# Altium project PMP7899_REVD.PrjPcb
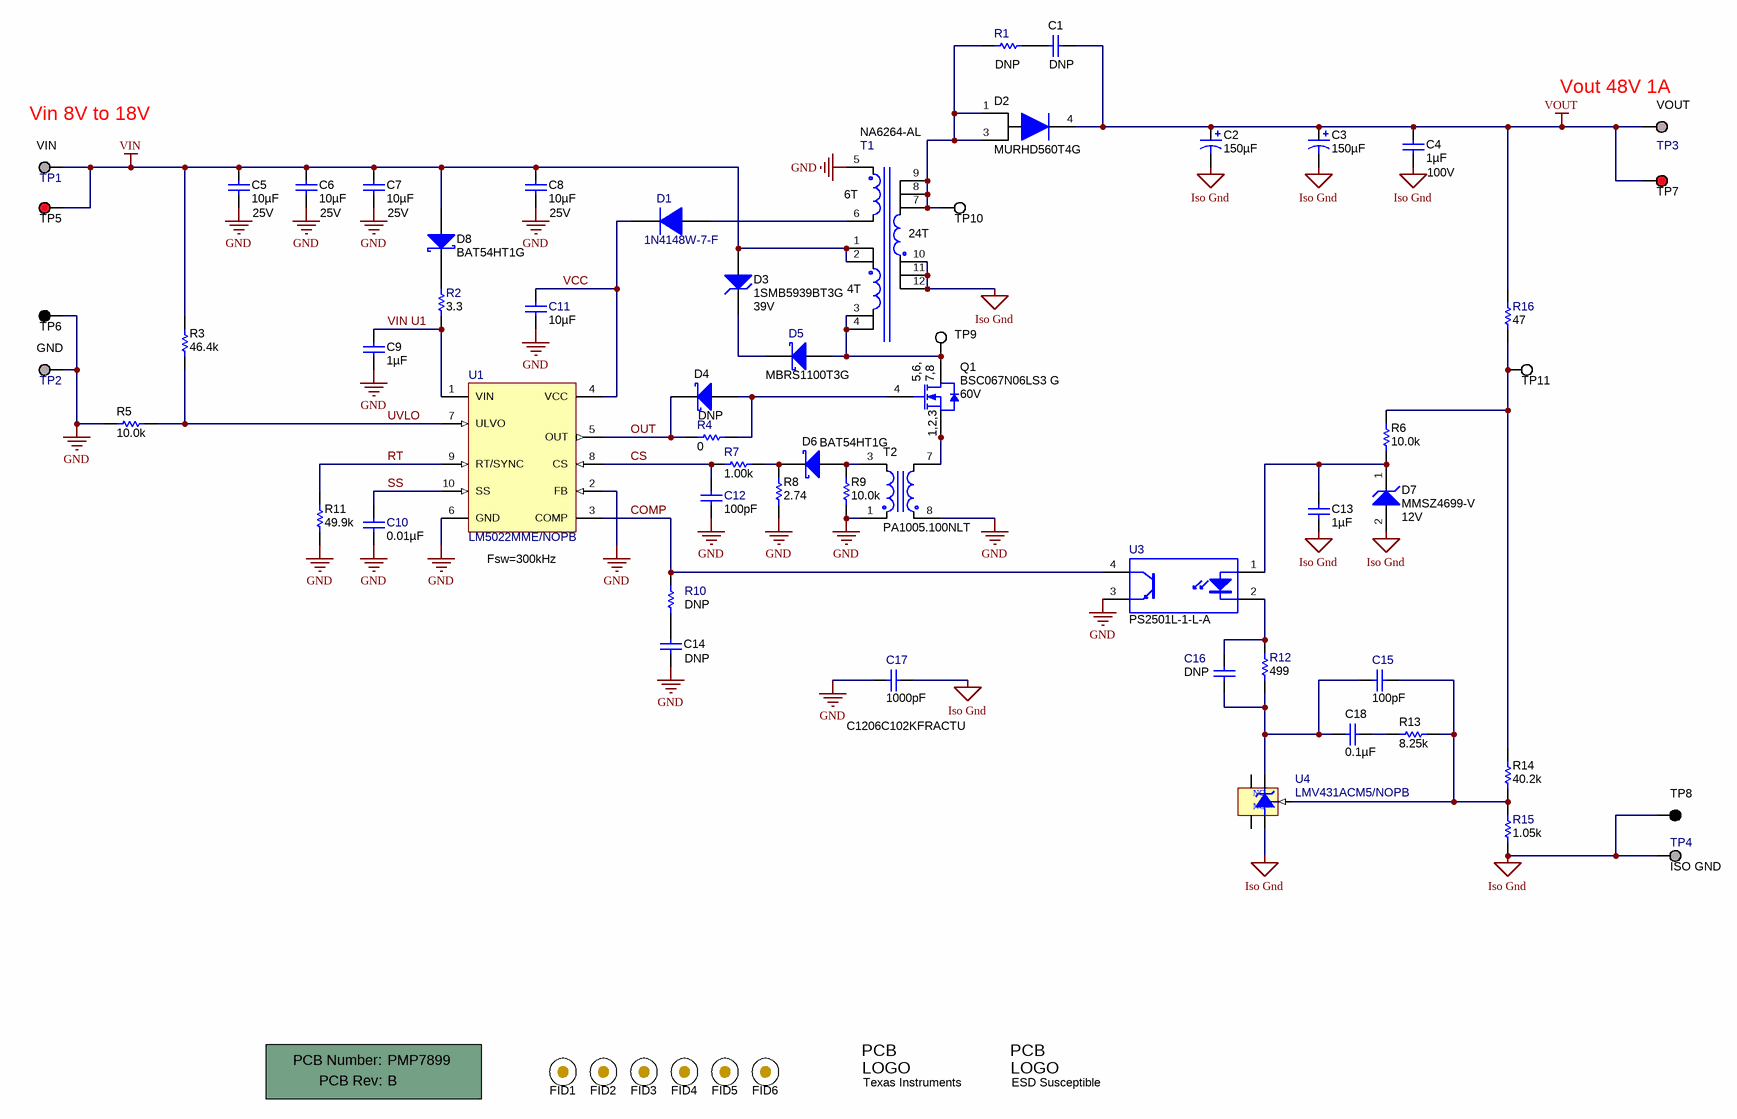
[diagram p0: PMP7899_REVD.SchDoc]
TID: PMP7899; TechSupport: http://www.ti.com/support; SCH_Rev: D; PRJ_Title: LM5022 Flyback; PRJ_Number: PMP7899; PRJ_Engineer: David Baba; PRJ_Customer: Public Release; PCB_Rev: B; PCB_Layout: Dee Lim; EVM_Orderable: N/A; CopyrightYear: 2015
1 sheet, 68 parts. Net scope: global (net labels, ports and power ports of the same name join across sheets).
Board file: PMP7899_REVB.PcbDoc

## Sheet PMP7899_REVD.SchDoc
size 431 x 279 mm; Date: Not shown in title block; ApprovedBy: Not shown in title block; CheckedBy: Not shown in title block; Author: Not shown in title block; CompanyName: Not shown in title block; Engineer: Not shown in title block; Organization: Not shown in title block; Address1: Not shown in title block; Address2: Not shown in title block; Address3: Not shown in title block; Address4: Not shown in title block; DocumentNumber: 1; Revision: Use project parameter SCH_Rev; SheetNumber: 1; SheetTotal: 1; PageSetup: Record=PageOptions¦CenterHorizontal=True¦CenterVertical=True¦PrintScale=1.00¦XCorrection=1.00¦YCorrection=1.00¦PrintKind=0¦BorderSize=5000000¦LeftOffset=0¦BottomOffset=0¦Orientation=2¦PaperLength=1000¦PaperWidth=1000¦Scale=100¦PaperSource=15¦PrintQuality=600¦MediaType=1¦DitherType=10¦PaperKind=Letter¦PrintScaleMode=1

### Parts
!PCB  Printed Circuit Board  (value not drawn)  (mechanical)
C1  DNP  [0603]
C2  ValueDisplayed: 150µF  [SM_RADIAL_H13]  (hidden comment: EEV-FK1J151Q)
C3  ValueDisplayed: 150µF  [SM_RADIAL_H13]  (hidden comment: EEV-FK1J151Q)
C4  ValueDisplayed: 1µF  Value2: 100V  [1206]  (hidden comment: C3216X7R2A105M)
C5  ValueDisplayed: 10µF  VDC_V: 25V  [1206]  (hidden comment: GRM31CR71E106KA12L)
C6  ValueDisplayed: 10µF  VDC_V: 25V  [1206]  (hidden comment: GRM31CR71E106KA12L)
C7  ValueDisplayed: 10µF  VDC_V: 25V  [1206]  (hidden comment: GRM31CR71E106KA12L)
C8  ValueDisplayed: 10µF  VDC_V: 25V  [1206]  (hidden comment: GRM31CR71E106KA12L)
C9  ValueDisplayed: 1µF  [0805_HV]  (hidden comment: C2012X5R1E105K)
C10  ValueDisplayed: 0.01µF  [0805_HV]  (hidden comment: C2012C0G1E103J)
C11  ValueDisplayed: 10µF  [1206]  (hidden comment: GRM31CR61E106KA12L)
C12  ValueDisplayed: 100pF  [0603]  (hidden comment: C1608C0G1H101J)
C13  ValueDisplayed: 1µF  [0603]  (hidden comment: GRM188R61C105KA93D)
C14  DNP  [0603]
C15  ValueDisplayed: 100pF  [0603]  (hidden comment: C1608C0G2A101J)
C16  DNP  [0805_HV]
C17  C1206C102KFRACTU  ValueDisplayed: 1000pF  [1206]
C18  ValueDisplayed: 0.1µF  [0603]  (hidden comment: C0603C104J3RACTU)
D1  1N4148W-7-F  [SOD-123]
D2  MURHD560T4G  [DPAK]
D3  1SMB5939BT3G  value 39V  [SMB]
D4  DNP  [sod-323]
D5  MBRS1100T3G  [SMB]
D6  BAT54HT1G  [sod-323]
D7  MMSZ4699-V  value 12V  [SOD-123]
D8  BAT54HT1G  [sod-323]
FID1  Fiducial  [Fiducial10-20]  (value not drawn)
FID2  Fiducial  [Fiducial10-20]  (value not drawn)
FID3  Fiducial  [Fiducial10-20]  (value not drawn)
FID4  Fiducial  [Fiducial10-20]  (value not drawn)
FID5  Fiducial  [Fiducial10-20]  (value not drawn)
FID6  Fiducial  [Fiducial10-20]  (value not drawn)
Logo1  Texas Instruments  [TI_Symbol_Overlay_Small]  (no BOM)
Logo2  ESD Susceptible  [ESD_Overlay_Small]  (no BOM)
Q1  BSC067N06LS3 G  value 60V  [PG-TDSON-8]
R1  DNP  [1206]
R2  ValueDisplayed: 3.3  [1206]  (hidden comment: CRCW12063R30JNEA)
R3  value 46.4k  [0603]  (hidden comment: CRCW060346K4FKEA)
R4  value 0  [1206]  (hidden comment: CRCW12060000Z0EA)
R5  value 10.0k  [0603]  (hidden comment: CRCW060310K0FKEA)
R6  value 10.0k  [0805_HV]  (hidden comment: CRCW080510K0FKEA)
R7  value 1.00k  [0603]  (hidden comment: CRCW06031K00FKEA)
R8  ValueDisplayed: 2.74  [0603]  (hidden comment: CRCW06032R74FKEA)
R9  value 10.0k  [0603]  (hidden comment: CRCW060310K0FKEA)
R10  DNP  [0603]
R11  value 49.9k  [0603]  (hidden comment: CRCW060349K9FKEA)
R12  value 499  [0805_HV]  (hidden comment: CRCW0805499RFKEA)
R13  ValueDisplayed: 8.25k  [0603]  (hidden comment: CRCW06038K25FKEA)
R14  value 40.2k  [0603]  (hidden comment: CRCW060340K2FKEA)
R15  ValueDisplayed: 1.05k  [0603]  (hidden comment: CRCW06031K05FKEA)
R16  ValueDisplayed: 47  [0805_HV]  (hidden comment: ERJ-6GEYJ470V)
T1  NA6264-AL  [NA62XX-AL]
T2  PA1005.100NLT  [PA1005.XXXNL]
TP1  VIN  [Keystone1502-2]
TP2  GND  [Keystone1502-2]
TP3  VOUT  [Keystone1502-2]
TP4  ISO GND  [Keystone1502-2]
TP5  5000  [Keystone5000]  (value not drawn)
TP6  5001  [Keystone5001]  (value not drawn)
TP7  5000  [Keystone5000]  (value not drawn)
TP8  5001  [Keystone5001]  (value not drawn)
TP9  5002  [Keystone5002]  (value not drawn)
TP10  5002  [Keystone5002]  (value not drawn)
TP11  5002  [Keystone5002]  (value not drawn)
U1  LM5022MME/NOPB  [MUB10A_N]
U3  PS2501L-1-L-A  [PS2501L]
U4  LMV431ACM5/NOPB  [MF05A_N]

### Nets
GND: C5.2 C6.2 C7.2 C8.2 C9.2 C10.2 C11.2 C12.2 C14.2 C17.2 R5.1 R8.1 R9.1 R11.1 T1.5 T2.1 T2.8 TP2.1 TP6.1 U1.2(FB) U1.6(GND) U3.3(E)
Iso Gnd: C2.2(-) C3.2(-) C4.2 C13.2 C17.1 D7.2(A) R15.2 T1.10 T1.11 T1.12 TP4.1 TP8.1 U4.5(A)
VIN: C5.1 C6.1 C7.1 C8.1 D3.2(A) D8.2(A) R3.2 T1.1 T1.2 TP1.1 TP5.1
VOUT: C1.1 C2.1(+) C3.1(+) C4.1 D2.4 R16.2 TP3.1 TP7.1
COMP: R10.1 U1.3(COMP) U3.4(C)
CS: C12.1 R7.1 U1.8(CS)
OUT: D4.1(K) R4.2 U1.5(OUT)
RT: R11.2 U1.9(RT/SYNC)
SS: C10.1 U1.10(SS)
UVLO: R3.1 R5.2 U1.7(ULVO)
VCC: C11.1 D1.1(K) U1.4(VCC)
VIN U1: C9.1 R2.1 U1.1(VIN)
NetC1_2: C1.2 R1.1
NetC13_1: C13.1 D7.1(K) R6.1 U3.1(A)
NetC14_1: C14.1 R10.2
NetC15_1: C15.1 C16.1 C18.2 R12.2 U4.3(K)
NetC15_2: C15.2 R13.1 R14.1 R15.1 U4.4(REF)
NetC16_2: C16.2 R12.1 U3.2(K)
NetC18_1: C18.1 R13.2
NetD1_2: D1.2(A) T1.6
NetD2_1: D2.1 D2.3 R1.2 T1.7 T1.8 T1.9 TP10.1
NetD3_1: D3.1(K) D5.1(K)
NetD4_2: D4.2(A) Q1.4(G) R4.1
NetD5_2: D5.2(A) Q1.5(D) Q1.6(D) Q1.7(D) Q1.8(D) Q1.9(D) T1.3 T1.4 TP9.1
NetD6_1: D6.1(K) R7.2 R8.2
NetD6_2: D6.2(A) R9.2 T2.3
NetD8_1: D8.1(K) R2.2
NetQ1_1: Q1.1(S) Q1.2(S) Q1.3(S) T2.7
NetR6_2: R6.2 R14.2 R16.1 TP11.1

Not connected (* = marked no-connect by the designer): U4 1(NC) 2(NC)

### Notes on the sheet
- (near TP1) Vin 8V to 18V
- (near TP3) Vout 48V 1A
- (near U1) Fsw=300kHz

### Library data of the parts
!PCB = PCB: Manufacturer: Any; PartNumber: PMP7899; SymbolCreator: a0412235
C1 = C1608C0G2A101J: CAP, CERM, 100pF, 100V, +/-5%, C0G/NP0, 0603; Manufacturer: TDK; Polarized: N; CompType: Capacitor; U/M: EA; Cap_F: 0.0000000001; Tolerance_%: 5; ESR_Ohm: 0.1202; Value1: 0.1202 ohm; VDC_V: 100; TaMin_C: -55; TaMax_C: 125
C2 C3 = EEV-FK1J151Q: CAP, AL, 150uF, 63V, +/-20%, 0.16 ohm, SMD; Manufacturer: Panasonic; Polarized: Y; CompType: Capacitor; U/M: EA; Cap_F: 0.00015; Tolerance_%: 20; VDC_V: 63; ESR_Ohm: 0.16; IRMS_A: 0.8; TaMin_C: -55; TaMax_C: 105; Cap_Case: H13
C4 = C3216X7R2A105M: CAP, CERM, 1uF, 100V, +/-20%, C Series, 1206; Manufacturer: TDK; Polarized: N; CompType: Capacitor; U/M: EA; Cap_F: 0.000001; Tolerance_%: 20; ESR_Ohm: 0.006; Value1: 0.006 ohm; VDC_V: 100; IRMS_A: 4.5; TaMin_C: -55; TaMax_C: 125
C5-C8 = GRM31CR71E106KA12L: CAP, CERM, 10uF, 25V, +/-10%, X7R, 1206; Manufacturer: MuRata; Polarized: N; CompType: Capacitor; U/M: EA; Cap_F: 0.00001; Tolerance_%: 10; TaMin_C: -55; TaMax_C: 125; Cap_Case: 2220
C9 = C2012X5R1E105K: CAP, CERM, 1uF, 25V, +/-10%, X5R, 0805; Manufacturer: TDK; Polarized: N; CompType: Capacitor; U/M: EA; Cap_F: 0.000001; Tolerance_%: 10; ESR_Ohm: 0.0075; Value1: 0.0075 ohm; VDC_V: 25; TaMin_C: -55; TaMax_C: 85; Cap_Case: 0805
C10 = C2012C0G1E103J: CAP, CERM, 0.01uF, 25V, +/-5%, C0G/NP0, 0805; Manufacturer: TDK; Cap_Case: 0805; ESR_Ohm: 0.03; Polarized: N; TaMax_C: 125; TaMin_C: -55; Tolerance_%: 5; VDC_V: 25; Cap_F: 0.00000001; CompType: Capacitor; Value1: 0.03 ohm; U/M: EA
C11 = GRM31CR61E106KA12L: CAP, CERM, 10uF, 25V, +/-10%, X5R, 1206; Manufacturer: MuRata; ESR_Ohm: 0.004; Polarized: N; TaMax_C: 85; TaMin_C: -55; Tolerance_%: 10; VDC_V: 25; Cap_F: 0.00001; CompType: Capacitor; U/M: EA; Value1: 0.004 ohm
C12 = C1608C0G1H101J: CAP, CERM, 100pF, 50V, +/-5%, C0G/NP0, 0603; Manufacturer: TDK; ESR_Ohm: 0.1679; Polarized: N; TaMax_C: 125; TaMin_C: -55; Tolerance_%: 5; VDC_V: 50; Cap_F: 0.0000000001; CompType: Capacitor; Value1: 0.1679 ohm; U/M: EA
C13 = GRM188R61C105KA93D: CAP, CERM, 1uF, 16V, +/-10%, X5R, 0603; Manufacturer: MuRata; Polarized: N; CompType: Capacitor; U/M: EA; Cap_F: 0.000001; Tolerance_%: 10; VDC_V: 16; TaMin_C: -55; TaMax_C: 85
C14 = C0603C104K3RACTU: CAP, CERM, 0.1uF, 25V, +/-10%, X7R, 0603; Manufacturer: Kemet; Polarized: N; CompType: Capacitor; ValueDisplayed: 0.1µF; U/M: EA; Cap_F: 0.0000001; Tolerance_%: 10; VDC_V: 25; TaMin_C: -55; TaMax_C: 125
C15 = C1608C0G2A101J: CAP, CERM, 100pF, 100V, +/-5%, C0G/NP0, 0603; Manufacturer: TDK; ESR_Ohm: 0.1202; Polarized: N; TaMax_C: 125; TaMin_C: -55; Tolerance_%: 5; VDC_V: 100; Cap_F: 0.0000000001; CompType: Capacitor; Value1: 0.1202 ohm; U/M: EA
C16 = C2012X7R1H102K: CAP, CERM, 1000 pF, 50 V, +/- 10%, X7R, 0805; Manufacturer: TDK; Cap_Case: 0805; ESR_ohm: 0.28; Polarized: N; TaMax_C: 125; TaMin_C: -55; Tolerance_%: 10; VDC_V: 50; Cap_F: 0.000000001; CompType: Capacitor; Value: 1000pF; Value1: 0.28 ohm; Value2: 50V; U/M: EA
C17 = C1206C102KFRACTU: CAP CER 1000PF 1.5KV X7R 1206; Manufacturer: Kemet; ESR_Ohm: 0.426; IRMS_A: 0.189; Polarized: N; TaMax_C: 125; TaMin_C: -55; Tolerance_%: 10; VDC_V: 1500; Cap_F: 0.000000001; CompType: Capacitor; Value1: 0.426 ohm; Value2: 1500V; U/M: EA
C18 = C0603C104J3RACTU: CAP, CERM, 0.1uF, 25V, +/-5%, X7R, 0603; Manufacturer: Kemet; Polarized: N; CompType: Capacitor; U/M: EA; Cap_F: 0.0000001; Tolerance_%: 5; VDC_V: 25; TaMin_C: -55; TaMax_C: 125
D1 = 1N4148W-7-F: Diode, Ultrafast, 100V, 0.15A, SOD-123; Manufacturer: Diodes Inc.; U/M: EA; Vf_V: 1.25; Io_A: 0.15; Vr_V: 100; TJmax_C: 150; Value: 1.25V
D2 = MURHD560T4G: Ultra-Fast Diode 600V, 5A, DPAK; Manufacturer: ON Semiconductor
D3 = 1SMB5939BT3G: Diode, Zener, 39 V, 550 mW, SMB; Manufacturer: ON Semiconductor; U/M: EA; Power_W: 0.55; Value1: 0.55W; RJA_CperW: 226; SymbolCreator: a0412235; Vz_V: 39
D4 D6 D8 = BAT54HT1G: Diode, Schottky, 30V, 0.2A, SOD-323; Manufacturer: ON Semiconductor; Value: 0.35V; U/M: EA; Vf_V: 0.35; Io_A: 0.2; Vr_V: 30
D5 = MBRS1100T3G: Diode, Schottky, 100 V, 1 A, SMB; Manufacturer: ON Semiconductor; RJC_CperW: 22; Vf_V: 0.75; Io_A: 1; Vr_V: 100; TJmax_C: 150; Value: 100V; U/M: EA; Value1: 1A; Value2: 0.75V
D7 = MMSZ4699-V: Diode, Zener, 12V, 500mW, SOD-123; Manufacturer: Vishay-Semiconductor; U/M: EA; Power_W: 0.5; Vz: 12; Value1: 0.5W; RJA_CperW: 67
FID1-FID6 = Fiducial: Fiducial mark.  There is nothing to buy or mount.; SymbolCreator: codlsc
Logo1 = TI_Logo: Texas Instrument Corporate Signature; SymbolCreator: codlsc
Logo2 = ESD_Susceptible: ESD Susceptible Symbol; SymbolCreator: codlsc
Q1 = BSC067N06LS3 G: MOSFET, N-CH, 60V, 50A, PG-TDSON-8; Manufacturer: Infineon Technologies; U/M: EA; ChType: N; VdsMax_V: 60; Value1: 0.0121 ohm; Rdson45_Ohm: 0.0121; Value2: 23 nC; QgTyp_nC: 23; Vgs_V: 20; IdsMax_A: 50
R1 = CRCW1206100RFKEA: RES, 100, 1%, 0.25 W, 1206; Manufacturer: Vishay-Dale; CompType: Resistor; Tolerance_%: 1; VDC_V: 200; Power_W: 0.25; Res_ohm: 100; Value: 100; Value_Code: 100R; Value2: 0.25W; TempCo: 100 ppm/C; EIA_Code: E96; U/M: EA
R2 = CRCW12063R30JNEA: RES, 3.3, 5%, 0.25 W, 1206; Manufacturer: Vishay-Dale; CompType: Resistor; Tolerance_%: 5; VDC_V: 200; Power_W: 0.25; Value: 3.3; Value_Code: 3R30; Value2: 0.25W; EIA_Code: E24; U/M: EA; TempCo: 200 ppm/C
R3 = CRCW060346K4FKEA: RES, 46.4k ohm, 1%, 0.1W, 0603; Manufacturer: Vishay-Dale; CompType: Resistor; Res_ohm: 46400; Value_Code: 46k4; Tolerance_%: 1; Power_W: 0.1; VDC_V: 75; TempCo: 100 ppm/C; EIA_Code: E96; U/M: EA
R4 = CRCW12060000Z0EA: RES, 0 ohm, 5%, 0.25W, 1206; Manufacturer: Vishay-Dale; Alternate PartNumber: Equivalent; Alternate Manufacturer: Any; CompType: Resistor; Tolerance_%: 5; VDC_V: 200; Power_W: 0.25; Value_Code: 0000; EIA_Code: E24; U/M: EA; TempCo: 200 ppm/C
R5 R9 = CRCW060310K0FKEA: RES, 10.0k ohm, 1%, 0.1W, 0603; Manufacturer: Vishay-Dale; CompType: Resistor; Res_ohm: 10000; Value_Code: 10k0; Tolerance_%: 1; Power_W: 0.1; VDC_V: 75; TempCo: 100 ppm/C; EIA_Code: E96; U/M: EA
R6 = CRCW080510K0FKEA: RES, 10.0k ohm, 1%, 0.125W, 0805; Manufacturer: Vishay-Dale; CompType: Resistor; Res_ohm: 10000; Value_Code: 10k0; Tolerance_%: 1; Power_W: 0.125; VDC_V: 150; TempCo: 100 ppm/C; EIA_Code: E96; U/M: EA
R7 R10 = CRCW06031K00FKEA: RES, 1.00k ohm, 1%, 0.1W, 0603; Manufacturer: Vishay-Dale; Alternate Manufacturer: Any; Alternate PartNumber: Equivalent; CompType: Resistor; Tolerance_%: 1; VDC_V: 75; Power_W: 0.1; Res_ohm: 1000; Value_Code: 1k00; TempCo: 100 ppm/C; EIA_Code: E96; U/M: EA
R8 = CRCW06032R74FKEA: RES, 2.74, 1%, 0.1 W, 0603; Manufacturer: Vishay-Dale; CompType: Resistor; Value: 2.74; Value_Code: 2R74; Tolerance_%: 1; Power_W: 0.1; Value2: 0.1W; VDC_V: 75; TempCo: 100 ppm/C; EIA_Code: E96; U/M: EA
R11 = CRCW060349K9FKEA: RES, 49.9k ohm, 1%, 0.1W, 0603; Manufacturer: Vishay-Dale; CompType: Resistor; Res_ohm: 49900; Value_Code: 49k9; Tolerance_%: 1; Power_W: 0.1; VDC_V: 75; TempCo: 100 ppm/C; EIA_Code: E96; U/M: EA
R12 = CRCW0805499RFKEA: RES, 499 ohm, 1%, 0.125W, 0805; Manufacturer: Vishay-Dale; Alternate Manufacturer: Any; Alternate PartNumber: Equivalent; CompType: Resistor; Tolerance_%: 1; VDC_V: 150; Power_W: 0.125; Value_Code: 499R; TempCo: 100 ppm/C; EIA_Code: E96; U/M: EA
R13 = CRCW06038K25FKEA: RES, 8.25 k, 1%, 0.1 W, 0603; Manufacturer: Vishay-Dale; CompType: Resistor; Value: 8.25k; Res_ohm: 8250; Value_Code: 8k25; Tolerance_%: 1; Power_W: 0.1; Value2: 0.1W; VDC_V: 75; TempCo: 100 ppm/C; EIA_Code: E96; U/M: EA
R14 = CRCW060340K2FKEA: RES, 40.2k ohm, 1%, 0.1W, 0603; Manufacturer: Vishay-Dale; CompType: Resistor; Res_ohm: 40200; Value_Code: 40k2; Tolerance_%: 1; Power_W: 0.1; VDC_V: 75; TempCo: 100 ppm/C; EIA_Code: E96; U/M: EA
R15 = CRCW06031K05FKEA: RES, 1.05 k, 1%, 0.1 W, 0603; Manufacturer: Vishay-Dale; CompType: Resistor; Tolerance_%: 1; VDC_V: 75; Power_W: 0.1; Res_ohm: 1050; Value: 1.05k; Value_Code: 1k05; Value2: 0.1W; TempCo: 100 ppm/C; EIA_Code: E96; U/M: EA
R16 = ERJ-6GEYJ470V: RES, 47, 5%, 0.125 W, 0805; Manufacturer: Panasonic; CompType: Resistor; Tolerance_%: 5; VDC_V: 150; Power_W: 0.125; Value: 47; Value_Code: 47R0; Value2: 0.125W; EIA_Code: E24; U/M: EA; TempCo: 200 ppm/C
T1 = NA6264-AL: COILCRAFT TRANSFORMER; U/M: EA; Ns1toNp: 24;4
T2 = PA1005.100NLT: XFRMR CURR SENSE 2.0MH 1:100 SMD; Manufacturer: Pulse Engineering; CompType: Transformer; Rp: .000750; U/M: EA
TP1-TP4 = 1502-2: Terminal, Turret, TH, Double; Manufacturer: Keystone; Alternate Manufacturer: Any; Alternate PartNumber: Equivalent; CompType: Turret Terminal; U/M: EA
TP5 TP7 = 5000: Test Point, TH, Miniature, Red; Manufacturer: Keystone; Alternate Manufacturer: Any; Alternate PartNumber: Equivalent; CompType: Test Point Loop; U/M: EA
TP6 TP8 = 5001: Test Point, TH, Miniature, Black; Manufacturer: Keystone; Alternate Manufacturer: Any; Alternate PartNumber: Equivalent; CompType: Test Point Loop; U/M: EA
TP9-TP11 = 5002: Test Point, TH, Miniature, White; Manufacturer: Keystone; Alternate Manufacturer: Any; Alternate PartNumber: Equivalent; CompType: Test Point Loop; U/M: EA
U1 = LM5022MME/NOPB: 60V Low Side Controller for Boost and SEPIC, 10-pin MSOP, Pb-Free; Manufacturer: Texas Instruments; CompType: Switcher; PackageTopMarking: ZXTT*5022; PowerWise: Y
U3 = PS2501L-1-L-A: High Isolation Voltage Single Transistor Type OptoCoupler 200-400% CTR; Manufacturer: California Eastern Laboratories; U/M: EA; Current Transfer Ratio (Min): 200% @ 5mA; Current Transfer Ratio (Max): 400% @ 5mA
U4 = LMV431ACM5/NOPB: Low-Voltage (1.24V) Adjustable Precision Shunt Regulators, 5-pin SOT-23, Pb-Free; Manufacturer: Texas Instruments; PackageTopMarking: N09A*XTT; PowerWise: N; CompType: MiscPower

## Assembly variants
001: not fitted C1 C14 C16 D4 R1 R10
